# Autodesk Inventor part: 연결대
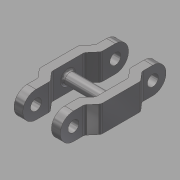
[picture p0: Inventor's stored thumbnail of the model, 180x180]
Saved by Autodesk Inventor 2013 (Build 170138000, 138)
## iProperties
Created: 2017-10
Part Number: 연결대
Material: 스테인리스강
Document SubType Name: Modeling
Designer: mduedu
Density: 1 g/cm^3
Author: mduedu
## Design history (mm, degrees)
sketch "스케치1"
  geometry: L1 (10, -7.497)-(10, 0); L2 (10, 0)-(14, 0); L3 (14, 0)-(14, -9); L4 (10.5, -24)-(6.5, -24); L5 (6.5, -24)-(6.5, -11.497); L6 (10.5, -13)-(10.5, -24); L7 (10.5, -13)-(14, -9); L8 (6.5, -11.497)-(10, -7.497); L9 (0, 0)-(10, 0); L10 (10, 7.497)-(10, 0); L11 (14, 0)-(14, 9); L12 (10.5, 24)-(6.5, 24); L13 (6.5, 24)-(6.5, 11.497); L14 (10.5, 13)-(10.5, 24); L15 (10.5, 13)-(14, 9); L16 (6.5, 11.497)-(10, 7.497)
  constraints: 32 end point, 6 symmetric about line, 4 parallel, 2 horizontal, 1 collinear, 1 horizontal alignment, 1 perpendicular, 1 vertical
  dimensions: "d0" = 10 distance from line of L1 L9.start; "d1" = 4 distance of L1.end L2.end; "d2" = 6.5 distance from line of L5 L9.start; "d4" = 24 distance between parallel lines of L4 L2; "d5" = 4 distance between parallel lines of L8 L7; "d6" = 9 distance of L2.end L3.end; "d7" = 11 distance of L6.start L4.start
extrude "돌출1" new body sketch "스케치1" distance "d8" = 12; taper "d9" = 0 deg
fillet "모깎기1"
fillet "모깎기2"
fillet "모깎기3" dims "d10" = 2, "d11" = 2
sketch "스케치2"
  geometry: L1 (-5.689, 12)-(-5.689, 0) reference; L2 (19.18, 0)-(19.18, 12) reference; L3 (-5.689, 6)-(19.18, 6); C1 r 2.5 at (6.746, 6); 1 further point
  constraints: 3 midpoint, 2 end point, 1 centre point, 1 vertical alignment
  dimensions: "d12" = 5 diameter of C1
extrude "돌출2" join sketch "스케치2" stored distance "d13" = 12; taper "d14" = 0 deg
fillet "모깎기4" dims "d15" = 1
sketch "스케치3"
  geometry: C1 r 2.5 at (0, 6); C2 r 2.5 at (36, 6); A1 r 6 centre (0, 6) between (0, 12) and (0, 0) reference; A2 r 6 centre (36, 6) between (36, 0) and (36, 12) reference; 1 further point
  constraints: 2 centre point, 2 coincident
  dimensions: "d16" = 5 diameter of C1; "d17" = 5 diameter of C2 (= d16)
extrude "돌출3" cut sketch "스케치3" stored distance "d18" = 12; taper "d19" = 0 deg
node "솔리드1"
mirror "대칭1"
